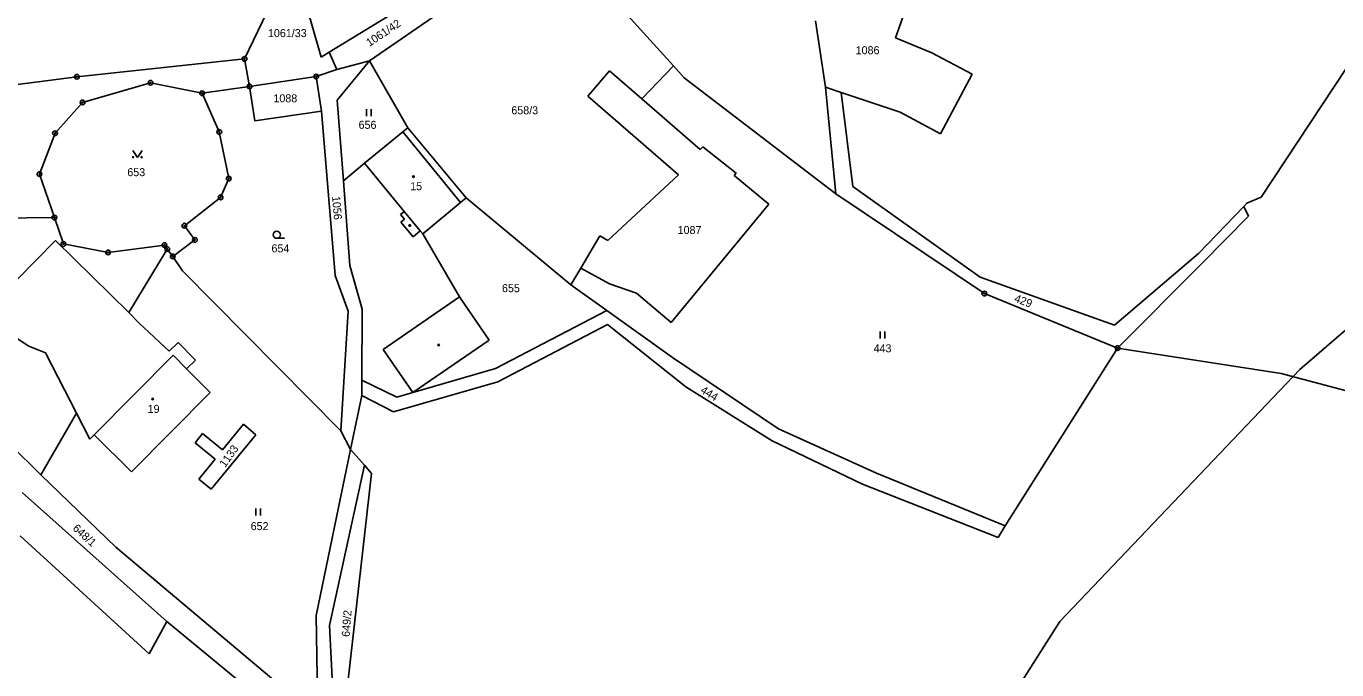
# Model space of a CAD drawing. Extents: x -547623 to -538651, y -1096714 to -1086522.
# Drawn here: x -542349 to -542070.7, y -1092948.3 to -1092811.5 of the extents above; entities that cross this region are included whole.
import ezdxf

# ---------------------------------------------------------------- set-up
doc = ezdxf.new("R2010")
doc.units = 0
for name, color, linetype in [('Vrstva 1', 7, 'Continuous'), ('Vrstva 25', 7, 'Continuous'), ('Vrstva 33', 7, 'Continuous'), ('Vrstva 52', 7, 'Continuous'), ('Vrstva 83', 7, 'Continuous'), ('Vrstva 86', 7, 'Continuous'), ('Vrstva 90', 7, 'Continuous'), ('Vrstva 92', 7, 'Continuous')]:
    doc.layers.add(name, color=color, linetype=linetype)

msp = doc.modelspace()

# ---------------------------------------------------------------- linework, layer by layer
at = {"layer": 'Vrstva 1'}
for points in [[(-542286.35, -1092818.11), (-542297.67, -1092778.8)], [(-542211.58, -1092819.95), (-542236.9, -1092791.94)], [(-542302.64, -1092818.46), (-542294.99, -1092802.54)], [(-542284.66, -1092817.06), (-542262.96, -1092803.73)], [(-542161.32, -1092805.12), (-542164.37, -1092813.99)], [(-542276.08, -1092818.85), (-542260.45, -1092808.15)], [(-542179.24, -1092824.49), (-542181.37, -1092810.41)], [(-542086.71, -1092847.83), (-542063.48, -1092812.56)], [(-542164.37, -1092813.99), (-542156.7, -1092817.17)], [(-542338.26, -1092822.26), (-542302.64, -1092818.46)], [(-542301.58, -1092824.33), (-542302.64, -1092818.46)], [(-542286.35, -1092818.11), (-542284.66, -1092817.06)], [(-542284.66, -1092817.06), (-542283.08, -1092820.7)], [(-542156.7, -1092817.17), (-542148.09, -1092821.75)], [(-542287.42, -1092822.23), (-542283.08, -1092820.7)], [(-542283.08, -1092820.7), (-542276.08, -1092818.85)], [(-542282.96, -1092827.26), (-542276.08, -1092818.85)], [(-542267.99, -1092833.09), (-542276.08, -1092818.85)], [(-542229.77, -1092826.4), (-542225.11, -1092821.03)], [(-542218.28, -1092826.96), (-542225.11, -1092821.03)], [(-542218.28, -1092826.96), (-542211.58, -1092819.95)], [(-542209.27, -1092822.5), (-542211.58, -1092819.95)], [(-542350.88, -1092823.94), (-542338.26, -1092822.26)], [(-542322.62, -1092823.55), (-542337.04, -1092827.72)], [(-542311.68, -1092825.77), (-542322.62, -1092823.55)], [(-542287.42, -1092822.23), (-542301.58, -1092824.33)], [(-542286.33, -1092829.55), (-542287.42, -1092822.23)], [(-542177.04, -1092847.11), (-542209.27, -1092822.5)], [(-542148.09, -1092821.75), (-542154.83, -1092834.39)], [(-542301.58, -1092824.33), (-542311.68, -1092825.77)], [(-542311.68, -1092825.77), (-542308.01, -1092833.97)], [(-542301.58, -1092824.33), (-542300.49, -1092831.65)], [(-542210.52, -1092843.12), (-542229.77, -1092826.4)], [(-542177.04, -1092847.11), (-542179.24, -1092824.49)], [(-542175.97, -1092825.59), (-542179.24, -1092824.49)], [(-542163.44, -1092829.81), (-542175.97, -1092825.59)], [(-542175.97, -1092825.59), (-542173.45, -1092845.6)], [(-542337.04, -1092827.72), (-542342.91, -1092834.28)], [(-542300.49, -1092831.65), (-542286.33, -1092829.55)], [(-542286.33, -1092829.55), (-542283.39, -1092864.51)], [(-542281.65, -1092844.35), (-542282.96, -1092827.26)], [(-542218.28, -1092826.96), (-542205.86, -1092837.75)], [(-542154.83, -1092834.39), (-542163.44, -1092829.81)], [(-542342.91, -1092834.28), (-542346.22, -1092842.95)], [(-542308.01, -1092833.97), (-542306, -1092843.91)], [(-542277.16, -1092840.65), (-542269.06, -1092833.97)], [(-542269.06, -1092833.97), (-542267.99, -1092833.09)], [(-542255.56, -1092847.98), (-542267.99, -1092833.09)], [(-542205.86, -1092837.75), (-542205.32, -1092837.14)], [(-542205.32, -1092837.14), (-542198.27, -1092842.76)], [(-542281.65, -1092844.35), (-542277.16, -1092840.65)], [(-542346.22, -1092842.95), (-542343.05, -1092852.18)], [(-542225.5, -1092857.05), (-542210.52, -1092843.12)], [(-542198.65, -1092843.22), (-542198.27, -1092842.76)], [(-542191.3, -1092849.31), (-542198.65, -1092843.22)], [(-542306, -1092843.91), (-542307.73, -1092847.89)], [(-542280.27, -1092862.38), (-542281.65, -1092844.35)], [(-542173.45, -1092845.6), (-542146.44, -1092864.88)], [(-542307.73, -1092847.89), (-542315.44, -1092853.91)], [(-542256.79, -1092849), (-542264.82, -1092855.62)], [(-542255.56, -1092847.98), (-542256.79, -1092849)], [(-542255.56, -1092847.98), (-542233.32, -1092866.49)], [(-542177.04, -1092847.11), (-542145.53, -1092868.35)], [(-542090.44, -1092849.81), (-542089.75, -1092849.1)], [(-542089.75, -1092849.1), (-542086.71, -1092847.83)], [(-542212.07, -1092874.46), (-542191.3, -1092849.31)], [(-542100.08, -1092859.79), (-542090.44, -1092849.81)], [(-542099.24, -1092861.89), (-542089.43, -1092851.86)], [(-542089.43, -1092851.86), (-542090.44, -1092849.81)], [(-542360.86, -1092852.4), (-542343.05, -1092852.18)], [(-542343.05, -1092852.18), (-542341.12, -1092857.8)], [(-542313.2, -1092856.92), (-542315.44, -1092853.91)], [(-542355.1, -1092869.5), (-542342.78, -1092857.04)], [(-542342.78, -1092857.04), (-542327.26, -1092872.39)], [(-542317.89, -1092860.44), (-542313.2, -1092856.92)], [(-542264.82, -1092855.62), (-542256.98, -1092869.05)], [(-542227.23, -1092856.04), (-542231.26, -1092862.95)], [(-542227.23, -1092856.04), (-542225.5, -1092857.05)], [(-542341.12, -1092857.8), (-542331.63, -1092859.58)], [(-542331.63, -1092859.58), (-542319.68, -1092858.04)], [(-542319.06, -1092858.88), (-542327.26, -1092872.39)], [(-542319.68, -1092858.04), (-542319.06, -1092858.88)], [(-542319.06, -1092858.88), (-542317.89, -1092860.44)], [(-542117.89, -1092875.08), (-542100.08, -1092859.79)], [(-542315.81, -1092863.52), (-542317.89, -1092860.44)], [(-542277.67, -1092871.68), (-542280.27, -1092862.38)], [(-542233.32, -1092866.49), (-542231.26, -1092862.95)], [(-542231.26, -1092862.95), (-542225.11, -1092866.3)], [(-542117.24, -1092879.91), (-542099.24, -1092861.89)], [(-542282.18, -1092897.51), (-542315.81, -1092863.52)], [(-542283.39, -1092864.51), (-542280.63, -1092872.1)], [(-542146.44, -1092864.88), (-542117.89, -1092875.08)], [(-542233.32, -1092866.49), (-542225.73, -1092871.93)], [(-542225.11, -1092866.3), (-542219.4, -1092868.26)], [(-542219.4, -1092868.26), (-542212.07, -1092874.46)], [(-542145.53, -1092868.35), (-542117.24, -1092879.91)], [(-542256.98, -1092869.05), (-542250.73, -1092878.22)], [(-542327.26, -1092872.39), (-542325.03, -1092874.6)], [(-542280.63, -1092872.1), (-542282.18, -1092897.51)], [(-542277.74, -1092886.75), (-542277.67, -1092871.68)], [(-542249.36, -1092884.25), (-542225.73, -1092871.93)], [(-542225.73, -1092871.93), (-542211.78, -1092881.95)], [(-542352.61, -1092876.72), (-542348.46, -1092879.52)], [(-542325.03, -1092874.6), (-542318.63, -1092880.57)], [(-542248.87, -1092887.12), (-542225.54, -1092874.89)], [(-542225.54, -1092874.89), (-542208.91, -1092888.15)], [(-542348.46, -1092879.52), (-542344.92, -1092880.96)], [(-542316.76, -1092878.74), (-542318.63, -1092880.57)], [(-542313.09, -1092882.46), (-542316.76, -1092878.74)], [(-542250.73, -1092878.22), (-542266.94, -1092889.37)], [(-542344.92, -1092880.96), (-542338.34, -1092893.73)], [(-542314.95, -1092884.3), (-542313.09, -1092882.46)], [(-542211.78, -1092881.95), (-542189.23, -1092897.11)], [(-542141.08, -1092917.69), (-542117.24, -1092879.91)], [(-542117.24, -1092879.91), (-542082.51, -1092885.3)], [(-542309.92, -1092889.39), (-542314.95, -1092884.3)], [(-542266.94, -1092889.37), (-542249.36, -1092884.25)], [(-542082.51, -1092885.3), (-542053.94, -1092892.92)], [(-542277.76, -1092890.02), (-542277.74, -1092886.75)], [(-542270.34, -1092890.36), (-542277.74, -1092886.75)], [(-542270.99, -1092893.44), (-542248.87, -1092887.12)], [(-542326.69, -1092906.24), (-542309.92, -1092889.39)], [(-542280.12, -1092901.48), (-542277.76, -1092890.02)], [(-542277.76, -1092890.02), (-542270.99, -1092893.44)], [(-542270.34, -1092890.36), (-542266.94, -1092889.37)], [(-542208.91, -1092888.15), (-542190.58, -1092899.59)], [(-542358.89, -1092894.11), (-542345.89, -1092906.86)], [(-542345.89, -1092906.86), (-542338.34, -1092893.73)], [(-542338.34, -1092893.73), (-542335.5, -1092899.24)], [(-542307.31, -1092901.57), (-542302.91, -1092896.11)], [(-542302.91, -1092896.11), (-542300.25, -1092898.33)], [(-542335.5, -1092899.24), (-542334.62, -1092898.35)], [(-542334.62, -1092898.35), (-542326.69, -1092906.24)], [(-542313.17, -1092900.07), (-542311.59, -1092898.1)], [(-542311.59, -1092898.1), (-542307.31, -1092901.57)], [(-542309.71, -1092909.9), (-542300.25, -1092898.33)], [(-542282.18, -1092897.51), (-542280.12, -1092901.48)], [(-542189.23, -1092897.11), (-542168.44, -1092906.51)], [(-542308.92, -1092903.55), (-542313.17, -1092900.07)], [(-542280.12, -1092901.48), (-542287.44, -1092936.71)], [(-542280.12, -1092901.48), (-542277.2, -1092904.81)], [(-542190.58, -1092899.59), (-542171.42, -1092908.8)], [(-542312.35, -1092907.8), (-542308.92, -1092903.55)], [(-542284.63, -1092938.85), (-542277.2, -1092904.81)], [(-542277.2, -1092904.81), (-542275.68, -1092906.55)], [(-542345.89, -1092906.86), (-542329.96, -1092922.21)], [(-542275.68, -1092906.55), (-542281.98, -1092962.29)], [(-542168.44, -1092906.51), (-542141.08, -1092917.69)], [(-542309.71, -1092909.9), (-542312.35, -1092907.8)], [(-542171.42, -1092908.8), (-542142.62, -1092920.13)], [(-542319.14, -1092938.02), (-542349.87, -1092910.57)], [(-542142.62, -1092920.13), (-542141.08, -1092917.69)], [(-542350.33, -1092919.79), (-542322.93, -1092944.91)], [(-542329.96, -1092922.21), (-542287.12, -1092958.35)], [(-542322.93, -1092944.91), (-542319.14, -1092938.02)], [(-542301.4, -1092952.67), (-542319.14, -1092938.02)], [(-542287.44, -1092936.71), (-542287.12, -1092958.35)], [(-542283.11, -1092968.36), (-542284.63, -1092938.85)]]:
    msp.add_lwpolyline(points, dxfattribs=at)
at = {"layer": 'Vrstva 25'}
for p, q in [((-542276.75, -1092830.65), (-542276.75, -1092829.15)), ((-542275.75, -1092830.65), (-542275.75, -1092829.15)), ((-542326.41, -1092837.91), (-542325.41, -1092839.41)), ((-542325.41, -1092839.41), (-542324.41, -1092837.91)), ((-542295.8, -1092856.59), (-542294.2, -1092856.59)), ((-542167.68, -1092877.89), (-542167.68, -1092876.39)), ((-542166.68, -1092877.89), (-542166.68, -1092876.39)), ((-542300.26, -1092915.51), (-542300.26, -1092914.01)), ((-542299.26, -1092915.51), (-542299.26, -1092914.01))]:
    msp.add_line(p, q, dxfattribs=at)
for centre, radius in [((-542326.31, -1092839.36), 0.112), ((-542324.51, -1092839.36), 0.112), ((-542266.78, -1092843.51), 0.175), ((-542267.56, -1092853.87), 0.175), ((-542295.8, -1092855.84), 0.75), ((-542261.42, -1092879.26), 0.175), ((-542322.16, -1092890.72), 0.175)]:
    msp.add_circle(centre, radius, dxfattribs=at)
at = {"layer": 'Vrstva 33'}
for points in [[(-542269.06, -1092833.97), (-542256.79, -1092849)], [(-542277.16, -1092840.65), (-542268.73, -1092850.87)], [(-542268.73, -1092850.87), (-542269.5, -1092851.51)], [(-542269.5, -1092851.51), (-542268.68, -1092852.51)], [(-542268.73, -1092850.87), (-542265.33, -1092855)], [(-542268.68, -1092852.51), (-542269.49, -1092853.18)], [(-542269.49, -1092853.18), (-542266.87, -1092856.27)], [(-542266.87, -1092856.27), (-542265.33, -1092855)], [(-542265.33, -1092855), (-542264.82, -1092855.62)], [(-542273.23, -1092880.23), (-542256.98, -1092869.05)], [(-542334.62, -1092898.35), (-542317.78, -1092881.44)], [(-542317.78, -1092881.44), (-542314.95, -1092884.3)], [(-542273.23, -1092880.23), (-542266.94, -1092889.37)]]:
    msp.add_lwpolyline(points, dxfattribs=at)
at = {"layer": 'Vrstva 52'}
msp.add_lwpolyline([(-542152, -1092973.5), (-542129.5, -1092938), (-542079.92, -1092885.99), (-542078.5, -1092884.5), (-542041.5, -1092852.5), (-541965.5, -1092801.5), (-541916.5, -1092774.5), (-541888.5, -1092765), (-541876, -1092767), (-541862, -1092780.5), (-541857, -1092794), (-541858, -1092816.5), (-541864.5, -1092835.5), (-541908.95, -1092918.72), (-541910.21, -1092921.09), (-541911.5, -1092923.5), (-541933, -1092986.5)], dxfattribs=at)
at = {"layer": 'Vrstva 83'}
for centre, radius in [((-542302.64, -1092818.46), 0.5), ((-542302.64, -1092818.46), 0.1), ((-542338.26, -1092822.26), 0.5), ((-542338.26, -1092822.26), 0.1), ((-542322.62, -1092823.55), 0.5), ((-542322.62, -1092823.55), 0.1), ((-542301.58, -1092824.33), 0.5), ((-542287.42, -1092822.23), 0.5), ((-542287.42, -1092822.23), 0.1), ((-542311.68, -1092825.77), 0.5), ((-542311.68, -1092825.77), 0.1), ((-542301.58, -1092824.33), 0.1), ((-542337.04, -1092827.72), 0.5), ((-542337.04, -1092827.72), 0.1), ((-542342.91, -1092834.28), 0.5), ((-542342.91, -1092834.28), 0.1), ((-542308.01, -1092833.97), 0.5), ((-542308.01, -1092833.97), 0.1), ((-542346.22, -1092842.95), 0.5), ((-542346.22, -1092842.95), 0.1), ((-542306, -1092843.91), 0.5), ((-542306, -1092843.91), 0.1), ((-542307.73, -1092847.89), 0.5), ((-542307.73, -1092847.89), 0.1), ((-542343.05, -1092852.18), 0.5), ((-542343.05, -1092852.18), 0.1), ((-542315.44, -1092853.91), 0.5), ((-542315.44, -1092853.91), 0.1), ((-542341.12, -1092857.8), 0.5), ((-542313.2, -1092856.92), 0.5), ((-542313.2, -1092856.92), 0.1), ((-542341.12, -1092857.8), 0.1), ((-542331.63, -1092859.58), 0.5), ((-542331.63, -1092859.58), 0.1), ((-542319.68, -1092858.04), 0.5), ((-542319.68, -1092858.04), 0.1), ((-542319.06, -1092858.88), 0.5), ((-542319.06, -1092858.88), 0.1), ((-542317.89, -1092860.44), 0.5), ((-542317.89, -1092860.44), 0.1), ((-542145.53, -1092868.35), 0.5), ((-542145.53, -1092868.35), 0.1), ((-542117.24, -1092879.91), 0.5), ((-542117.24, -1092879.91), 0.1)]:
    msp.add_circle(centre, radius, dxfattribs=at)
at = {"layer": 'Vrstva 90'}
for points in [[(-542277.16, -1092840.65), (-542269.06, -1092833.97)], [(-542269.06, -1092833.97), (-542256.79, -1092849)], [(-542277.16, -1092840.65), (-542268.73, -1092850.87)], [(-542256.79, -1092849), (-542264.82, -1092855.62)], [(-542268.73, -1092850.87), (-542265.33, -1092855)], [(-542265.33, -1092855), (-542264.82, -1092855.62)], [(-542334.62, -1092898.35), (-542317.78, -1092881.44)], [(-542317.78, -1092881.44), (-542314.95, -1092884.3)], [(-542309.92, -1092889.39), (-542314.95, -1092884.3)], [(-542326.69, -1092906.24), (-542309.92, -1092889.39)], [(-542334.62, -1092898.35), (-542326.69, -1092906.24)]]:
    msp.add_lwpolyline(points, dxfattribs=at)

# ---------------------------------------------------------------- texts
at = {"layer": 'Vrstva 86'}
for s, rotation, p in [('1061/42', 33.7091, (-542276.13, -1092815.92)), ('1056', 274.8967, (-542284.07, -1092847.68)), ('429', 339.0013, (-542139.31, -1092870)), ('444', 328.6815, (-542205.98, -1092889.28)), ('1133', 54.6755, (-542306.76, -1092905.41)), ('648/1', 317.6228, (-542339.29, -1092918.4)), ('649/2', 85.5123, (-542280.35, -1092941.33))]:
    msp.add_text(s, height=1.7, rotation=rotation, dxfattribs=at).set_placement(p)
for s, p in [('1061/33', (-542297.68, -1092813.84)), ('1086', (-542172.86, -1092817.48)), ('1088', (-542296.52, -1092827.7)), ('658/3', (-542245.99, -1092830.24)), ('656', (-542278.43, -1092833.33)), ('653', (-542327.55, -1092843.39)), ('1087', (-542210.67, -1092855.68)), ('654', (-542296.93, -1092859.58)), ('655', (-542247.98, -1092868.04)), ('443', (-542169.05, -1092880.82)), ('652', (-542301.35, -1092918.6))]:
    msp.add_text(s, height=1.7, dxfattribs=at).set_placement(p)
at = {"layer": 'Vrstva 92'}
for s, p in [('15', (-542267.48, -1092846.37)), ('19', (-542323.24, -1092893.68))]:
    msp.add_text(s, height=1.7, dxfattribs=at).set_placement(p)

doc.saveas('drawing.dxf')
